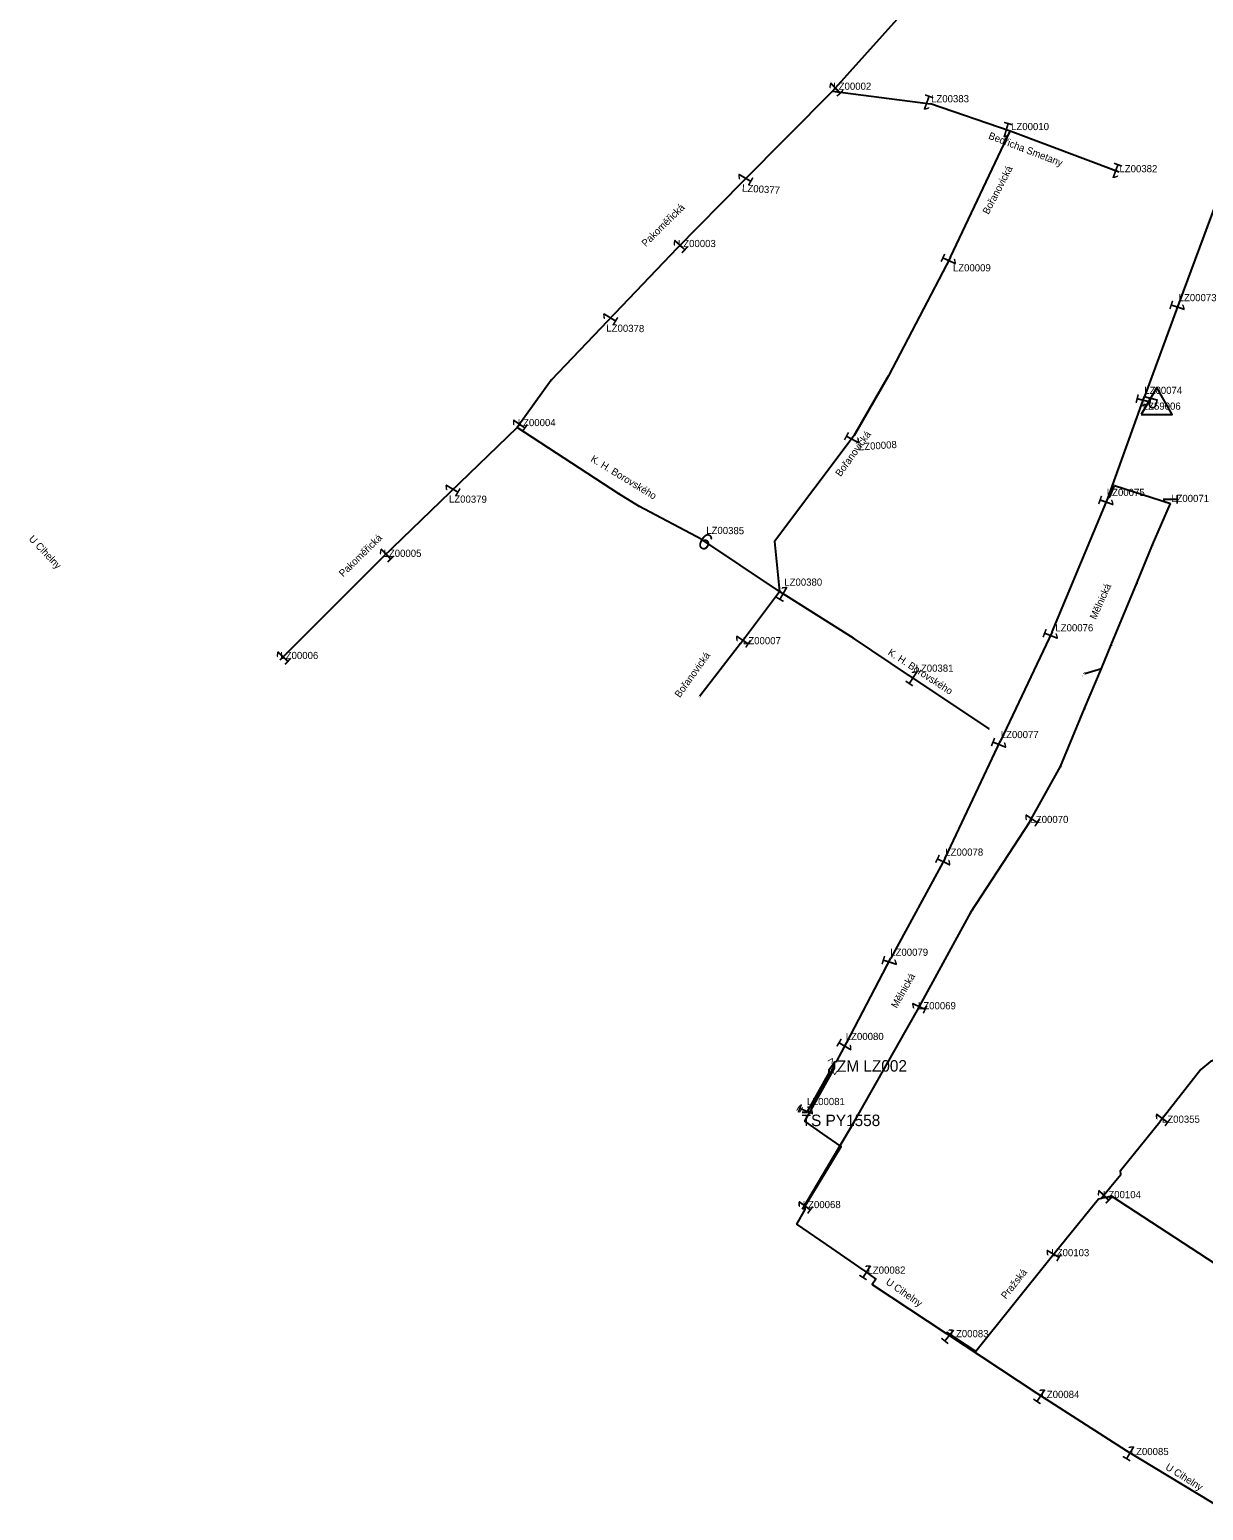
# Model space of a CAD drawing. Extents: x -736540 to -735418, y -1033000 to -1031598.
# Drawn here: x -736540 to -736132, y -1032856 to -1032341 of the extents above; entities that cross this region are included whole.
import ezdxf

# ---------------------------------------------------------------- set-up
doc = ezdxf.new("R2010")
doc.units = 0
for name, color, linetype in [('ftf_2010', 7, 'Continuous'), ('ftf_2050', 7, 'Continuous'), ('ftf_2060', 7, 'Continuous'), ('ftf_2240', 7, 'Continuous'), ('ftf_3010', 7, 'Continuous'), ('ftf_3010_ftf_3010_gtda_3015_gtda_3015_1', 7, 'Continuous'), ('ftf_3050', 7, 'Continuous'), ('ftf_3050_ftf_3050_gtda_3055_gtda_3055_1', 7, 'Continuous'), ('ftf_3130', 7, 'Continuous'), ('ftf_3150', 7, 'Continuous'), ('ftf_3150_ftf_3150_gtda_3155_gtda_3155_1', 7, 'Continuous'), ('ftf_3160', 7, 'Continuous'), ('ftf_3160_ftf_3160_gtda_3165_gtda_3165_1', 7, 'Continuous'), ('ftf_3170', 7, 'Continuous'), ('ftf_3240', 7, 'Continuous'), ('ftf_3270', 7, 'Continuous'), ('ftf_3270_ftf_3270_gtda_3275_gtda_3275_1', 7, 'Continuous'), ('ftf_nu', 7, 'Continuous')]:
    doc.layers.add(name, color=color, linetype=linetype)

msp = doc.modelspace()

# ---------------------------------------------------------------- linework, layer by layer
at = {"layer": 'ftf_2010'}
for points in [[(-736127.45, -1032401.33), (-736140.32, -1032436.02)], [(-736140.32, -1032436.02), (-736152.22, -1032468.46)], [(-736165.07, -1032503.95), (-736152.22, -1032468.46)], [(-736165.07, -1032503.95), (-736164.3, -1032503.44), (-736162.74, -1032499.51)], [(-736184.37, -1032550.41), (-736165.07, -1032503.95)], [(-736184.37, -1032550.41), (-736202.33, -1032588.35)], [(-736221.64, -1032629.17), (-736202.33, -1032588.35)], [(-736221.64, -1032629.17), (-736240.54, -1032664.04)], [(-736255.9, -1032693.4), (-736240.54, -1032664.04)], [(-736260.08, -1032700.09), (-736259.36, -1032699.83), (-736255.9, -1032693.4)], [(-736250.19, -1032772.44), (-736261.12, -1032764.89), (-736273.29, -1032756.56), (-736270.36, -1032751.45), (-736270.49, -1032750.48), (-736257.9, -1032729.52), (-736264.19, -1032725.12), (-736270.47, -1032720.72), (-736260.17, -1032702.28), (-736260.17, -1032700.42), (-736260.08, -1032700.09)], [(-736269.58, -1032715.86), (-736268.12, -1032715.71), (-736260.53, -1032702.12), (-736260.53, -1032700.85), (-736260.08, -1032700.09)], [(-736121.53, -1032699.55), (-736122.95, -1032699.23), (-736126.42, -1032698.96), (-736129.3, -1032699.91), (-736132.59, -1032702.72), (-736146.91, -1032720.92)], [(-736167.34, -1032747.62), (-736163.92, -1032743.45), (-736160.5, -1032739.29), (-736160.65, -1032737.93), (-736153.78, -1032729.43), (-736146.91, -1032720.92)], [(-736127.61, -1032770.37), (-736163.8, -1032746.89), (-736167.34, -1032747.62)], [(-736167.34, -1032747.62), (-736168.31, -1032747.92), (-736184.73, -1032768.17)], [(-736250.19, -1032772.44), (-736245.76, -1032775.68), (-736247.06, -1032777.59), (-736221.41, -1032794.56)], [(-736184.73, -1032768.17), (-736210.99, -1032800.91), (-736221.08, -1032794.29), (-736221.41, -1032794.56)], [(-736189.57, -1032815.57), (-736221.41, -1032794.56)], [(-736158.51, -1032835.5), (-736189.57, -1032815.57)], [(-736124.23, -1032856.21), (-736158.51, -1032835.5)]]:
    msp.add_lwpolyline(points, dxfattribs=at)
at = {"layer": 'ftf_2050'}
for points in [[(-736260.81, -1032362.16), (-736232.21, -1032330.19)], [(-736292.03, -1032393.62), (-736260.81, -1032362.16)], [(-736260.81, -1032362.16), (-736226.71, -1032366.65), (-736226.67, -1032366.68)], [(-736161.03, -1032390.44), (-736199.03, -1032376.09), (-736226.71, -1032366.65)], [(-736219.74, -1032419.93), (-736199.03, -1032376.09)], [(-736314.93, -1032416.87), (-736292.03, -1032393.62)], [(-736314.93, -1032416.87), (-736339.09, -1032442.19)], [(-736219.74, -1032419.93), (-736241.42, -1032461.24), (-736253.37, -1032482.1), (-736241.42, -1032461.24)], [(-736339.09, -1032442.19), (-736358.79, -1032462.83), (-736370.66, -1032479.27)], [(-736393.96, -1032501.82), (-736370.66, -1032479.27)], [(-736306.39, -1032518.3), (-736306.34, -1032518.27), (-736306.39, -1032518.3), (-736328.33, -1032506.66), (-736335.24, -1032502.34), (-736370.66, -1032479.27)], [(-736253.37, -1032482.1), (-736281.01, -1032518.92), (-736279.26, -1032536.37)], [(-736162.74, -1032499.51), (-736143.22, -1032505.69)], [(-736417.28, -1032524.35), (-736393.96, -1032501.82)], [(-736192.27, -1032616.69), (-736181.47, -1032597.25), (-736173.09, -1032577.05), (-736167.27, -1032563.11), (-736163.85, -1032554.97), (-736154.94, -1032533.45), (-736149.45, -1032520.07), (-736143.22, -1032505.69)], [(-736292.92, -1032554.46), (-736279.26, -1032536.37), (-736306.39, -1032518.3)], [(-736453.1, -1032560.11), (-736417.28, -1032524.35)], [(-736233.99, -1032565.72), (-736234.05, -1032565.68), (-736253.6, -1032552.62), (-736279.26, -1032536.37)], [(-736292.92, -1032554.46), (-736307.07, -1032572.84)], [(-736206.36, -1032584.2), (-736233.99, -1032565.72)], [(-736173.06, -1032564.94), (-736167.27, -1032563.11)], [(-736192.27, -1032616.69), (-736212.83, -1032648.15), (-736231.35, -1032682.13)], [(-736271.31, -1032751.37), (-736253.49, -1032721.14), (-736231.33, -1032682.11)]]:
    msp.add_lwpolyline(points, dxfattribs=at)
at = {"layer": 'ftf_2060'}
msp.add_lwpolyline([(-736271.48, -1032717.58), (-736269.72, -1032717.63), (-736261.98, -1032703.91), (-736261.98, -1032702.76), (-736260.08, -1032700.09)], dxfattribs=at)
at = {"layer": 'ftf_2240'}
msp.add_lwpolyline([(-736153.46, -1032474.76), (-736142.58, -1032474.76), (-736148.02, -1032465.33)], close=True, dxfattribs=at)

# ---------------------------------------------------------------- texts
at = {"layer": 'ftf_3010'}
for rotation, p in [(43.2385, (-736259.51, -1032364.5)), (160.2626, (-736225.22, -1032364.42)), (163.8283, (-736197.68, -1032373.77)), (59.7552, (-736290.11, -1032395.49)), (159.9849, (-736159.48, -1032388.22)), (47.45, (-736313.45, -1032419.1)), (245.4227, (-736221.84, -1032418.26)), (251.8943, (-736142.59, -1032434.6)), (58.7481, (-736337.21, -1032444.09)), (255.9575, (-736154.59, -1032467.2)), (55.5308, (-736368.88, -1032481.28)), (241.8745, (-736255.29, -1032480.37)), (59.4324, (-736392.06, -1032503.69)), (250.7016, (-736167.31, -1032502.48)), (90, (-736140.62, -1032506.34)), (44.6879, (-736415.91, -1032526.66)), (329.9199, (-736281.12, -1032538.29)), (248.7063, (-736186.55, -1032548.86)), (56.3427, (-736291.12, -1032556.44)), (47.1055, (-736451.64, -1032562.36)), (326.6248, (-736236.02, -1032567.49)), (248.1856, (-736204.5, -1032586.78)), (55.8676, (-736190.48, -1032618.68)), (244.2251, (-736223.7, -1032627.46)), (252.6383, (-736242.83, -1032662.65)), (64.8491, (-736229.25, -1032683.8)), (239.5227, (-736257.81, -1032691.52)), (248.0218, (-736271.74, -1032714.29)), (53.5887, (-736145.2, -1032722.98)), (45.5697, (-736165.94, -1032749.9)), (53.6094, (-736269.6, -1032753.43)), (59.7629, (-736182.81, -1032770.04)), (327.7961, (-736252.12, -1032774.3)), (321.1571, (-736223.54, -1032796.18)), (326.1679, (-736191.55, -1032817.37)), (329.3237, (-736160.39, -1032837.41))]:
    msp.add_text('1', height=5.2, rotation=rotation, dxfattribs=at).set_placement(p)
at = {"layer": 'ftf_3010_ftf_3010_gtda_3015_gtda_3015_1'}
for s, p in [('LZ00002', (-736260.57, -1032361.72)), ('LZ00383', (-736226.56, -1032366.08)), ('LZ00382', (-736160.98, -1032390.44)), ('LZ00003', (-736314.68, -1032416.48)), ('LZ00004', (-736370.44, -1032478.81)), ('LZ00005', (-736417.16, -1032524.31)), ('LZ00380', (-736277.66, -1032534.34)), ('LZ00007', (-736292.03, -1032554.72)), ('LZ00006', (-736453.07, -1032559.87)), ('LZ00381', (-736231.95, -1032564.29)), ('LZ00355', (-736146.18, -1032721.29)), ('LZ00104', (-736166.7, -1032747.54)), ('LZ00082', (-736248.68, -1032773.82)), ('LZ00083', (-736219.75, -1032795.94)), ('LZ00084', (-736188.13, -1032817.09)), ('LZ00085', (-736157.05, -1032836.97))]:
    msp.add_text(s, height=2.5, dxfattribs=at).set_placement(p)
for s, rotation, p in [('LZ00010', 0, (-736198.7, -1032375.76)), ('LZ00377', 356.3095, (-736292.42, -1032397.12)), ('LZ00009', 0, (-736218.97, -1032424.94)), ('LZ00073', 0, (-736140.37, -1032435.32)), ('LZ00378', 358.9583, (-736339.62, -1032445.86)), ('LZ00074', 0, (-736152.33, -1032467.58)), ('LZ00008', 3.822, (-736251.58, -1032487.27)), ('LZ00379', 359.4026, (-736394.4, -1032505.38)), ('LZ00075', 0, (-736165.39, -1032503.12)), ('LZ00071', 0, (-736142.98, -1032505.21)), ('LZ00076', 0.1236, (-736183.28, -1032550.25)), ('LZ00077', 0, (-736202.3, -1032587.41)), ('LZ00070', 0, (-736191.95, -1032616.95)), ('LZ00078', 0, (-736221.61, -1032628.32)), ('LZ00079', 0, (-736240.78, -1032663.17)), ('LZ00069', 0, (-736231.11, -1032681.78)), ('LZ00080', 0, (-736256.25, -1032692.49)), ('LZ00081', 0, (-736269.76, -1032715.14)), ('LZ00068', 0, (-736271.22, -1032751)), ('LZ00103', 0, (-736184.68, -1032767.74))]:
    msp.add_text(s, height=2.5, rotation=rotation, dxfattribs=at).set_placement(p)
at = {"layer": 'ftf_3050'}
msp.add_text('6', height=5.63, rotation=329.4749, dxfattribs=at).set_placement((-736308.33, -1032520.37))
at = {"layer": 'ftf_3050_ftf_3050_gtda_3055_gtda_3055_1'}
msp.add_text('LZ00385', height=2.5, rotation=359.4815, dxfattribs=at).set_placement((-736304.84, -1032516.31))
at = {"layer": 'ftf_3130'}
msp.add_text(':', height=1.6, rotation=335.1094, dxfattribs=at).set_placement((-736174.23, -1032565.74))
at = {"layer": 'ftf_3150'}
msp.add_text('>', height=2.7, rotation=55.4557, dxfattribs=at).set_placement((-736260.84, -1032701.2))
at = {"layer": 'ftf_3150_ftf_3150_gtda_3155_gtda_3155_1'}
msp.add_text('ZM LZ002', height=4, rotation=0.2392, dxfattribs=at).set_placement((-736259.32, -1032703.56))
at = {"layer": 'ftf_3160'}
msp.add_text('=', height=3.3, rotation=238.4712, dxfattribs=at).set_placement((-736272.96, -1032714.54))
at = {"layer": 'ftf_3160_ftf_3160_gtda_3165_gtda_3165_1'}
msp.add_text('TS PY1558', height=4, rotation=0.0326, dxfattribs=at).set_placement((-736271.6, -1032722.46))
at = {"layer": 'ftf_3170'}
msp.add_text('7', height=2.7, rotation=234.382, dxfattribs=at).set_placement((-736261.2, -1032701.66))
at = {"layer": 'ftf_3240'}
for p in [(-736359.19, -1032463.23), (-736163.14, -1032499.91), (-736335.64, -1032502.74), (-736328.73, -1032507.06), (-736149.85, -1032520.47), (-736155.34, -1032533.85), (-736254, -1032553.02), (-736164.25, -1032555.37), (-736173.46, -1032565.34), (-736167.67, -1032563.51), (-736307.47, -1032573.24), (-736173.49, -1032577.45), (-736206.76, -1032584.6), (-736181.87, -1032597.65), (-736213.23, -1032648.55), (-736253.89, -1032721.54)]:
    msp.add_text('G', height=0.8, dxfattribs=at).set_placement(p)
at = {"layer": 'ftf_3270'}
msp.add_text('R', height=4.8, rotation=255.8093, dxfattribs=at).set_placement((-736152.05, -1032467.78))
at = {"layer": 'ftf_3270_ftf_3270_gtda_3275_gtda_3275_1'}
msp.add_text('LZ59006', height=2.5, rotation=0, dxfattribs=at).set_placement((-736152.85, -1032473.08))
at = {"layer": 'ftf_nu'}
for s, rotation, p in [('Bedřicha Smetany', 339.0302, (-736206.8, -1032378.68)), ('Bořanovická', 62.4769, (-736206.57, -1032405.32)), ('Pakoměřická', 44.7774, (-736325.85, -1032416.54)), ('Bořanovická', 54.2808, (-736258.06, -1032496.58)), ('K. H. Borovského', 328.6273, (-736345.3, -1032490.91)), ('U Cihelny', 313.6036, (-736540.83, -1032518.24)), ('Pakoměřická', 44.4668, (-736431.21, -1032531.46)), ('Mělnická', 65.7521, (-736169.18, -1032546.32)), ('K. H. Borovského', 326.859, (-736241.82, -1032558.17)), ('Bořanovická', 54.2808, (-736314.03, -1032573.52)), ('Mělnická', 60.2863, (-736238.49, -1032681.62)), ('Pražská', 51.4792, (-736200.49, -1032782.84)), ('U Cihelny', 325.3236, (-736242.55, -1032777.27)), ('U Cihelny', 328.1232, (-736145.2, -1032841.8))]:
    msp.add_text(s, height=2.5, rotation=rotation, dxfattribs=at).set_placement(p)

doc.saveas('drawing.dxf')
